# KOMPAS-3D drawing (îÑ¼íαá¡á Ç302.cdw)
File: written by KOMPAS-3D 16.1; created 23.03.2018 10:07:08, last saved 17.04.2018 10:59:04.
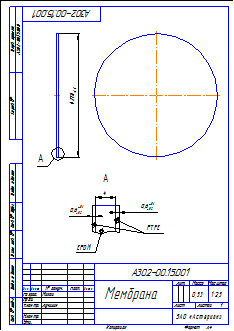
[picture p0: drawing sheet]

Sheet 1: A4, portrait

Title block, sheet 1: name: Мембрана; designation: А302-00.15.001; mass: 0,53; scale: 1:2,5; sheets: 1; organisation: ЗАО «Астерион»; sheet format: A4; stored path: \\192.168.87.28\Konstructor_doc\Мембранные насосы\Мембранный электропривод\А302-00.00.000 - ASTRA-302 (МЭ200)\Чертежи\А302-00.15.001 - Мембрана.cdw; drawn by: Милов; technical control: Лучихин

Views: Проекционный вид 2, Выносной элемент 3, Проекционный вид 4, Выносной элемент А, Выносной элемент
Referenced files in Z:\Мембранные насосы\Мембранный электропривод\А302-00.00.000 - ASTRA-302 (МЭ200)\3Д\: А302-00.15.001 - Мембрана.m3d
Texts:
  PTFE
  EPDM
Dimensions and other numbers on the sheet: 278; 4; 0,6; 1:2,5; 1; 0,53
